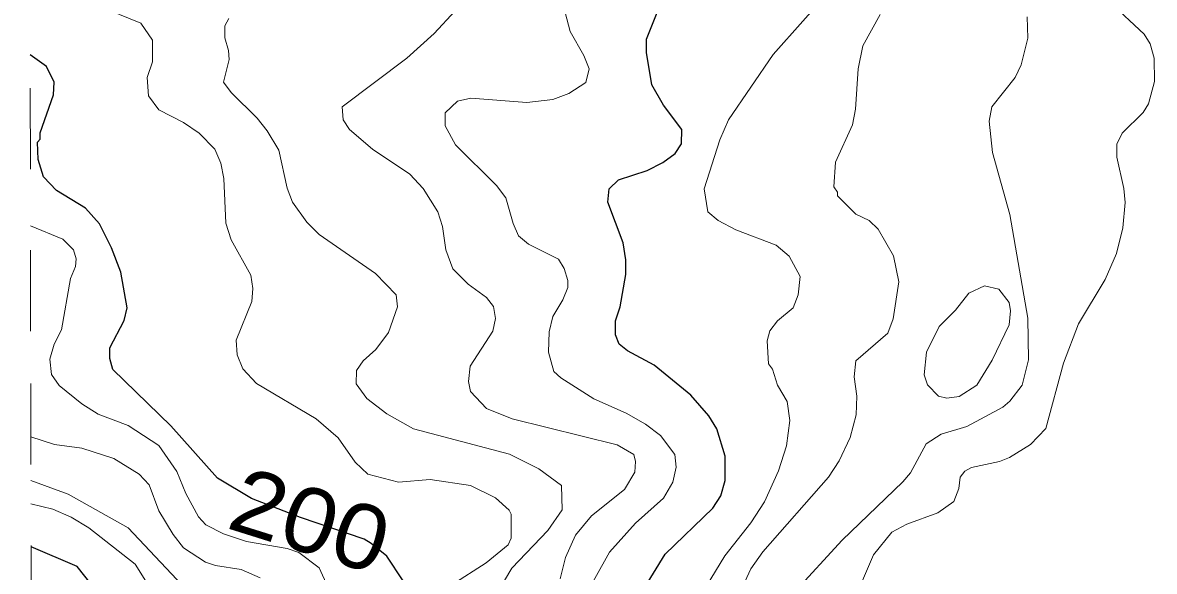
# Model space of a CAD drawing. Extents: x 474.5 to 500, y 7345.7 to 7373.4.
# Drawn here: x 474.522 to 475.921, y 7367.449 to 7368.127 of the extents above; entities that cross this region are included whole.
import ezdxf
from ezdxf.enums import TextEntityAlignment as Align

# ---------------------------------------------------------------- set-up
doc = ezdxf.new("R2010")
doc.units = 0
doc.header["$LTSCALE"] = 0.032
doc.linetypes.add('SHORT_DASHED', pattern=[2.7, 1.5, -1.2])
for name, color, linetype, lineweight in [('1', 7, 'Continuous', 25), ('2', 7, 'Continuous', 13), ('22', 7, 'SHORT_DASHED', 13)]:
    doc.layers.add(name, color=color, linetype=linetype, lineweight=lineweight)
doc.layers.add('61', color=7, linetype='Continuous')

msp = doc.modelspace()

# ---------------------------------------------------------------- linework, layer by layer
at = {"layer": '1'}
for points in [[(475.2879, 7367.4232), (475.3168, 7367.4701), (475.3756, 7367.5269), (475.3854, 7367.5423), (475.3909, 7367.5609), (475.391, 7367.5913), (475.3805, 7367.6247), (475.3706, 7367.6409), (475.3482, 7367.6664), (475.303, 7367.7036), (475.27, 7367.7211), (475.2598, 7367.7293), (475.2554, 7367.741), (475.2554, 7367.7584), (475.261, 7367.7755), (475.2681, 7367.8156), (475.2681, 7367.8337), (475.2646, 7367.8546), (475.2458, 7367.9048), (475.2475, 7367.9212), (475.259, 7367.9325), (475.2945, 7367.9441), (475.3139, 7367.9538), (475.3289, 7367.9652), (475.3367, 7367.9771), (475.3373, 7367.9949), (475.3145, 7368.0247), (475.3001, 7368.0497), (475.2937, 7368.09), (475.2937, 7368.1065), (475.3075, 7368.1415)], [(474.9929, 7367.4369), (474.9727, 7367.4674), (474.953, 7367.4832), (474.9446, 7367.4884), (474.8658, 7367.5155), (474.805, 7367.5389), (474.7631, 7367.5639), (474.7056, 7367.6285), (474.6336, 7367.698), (474.63, 7367.7118), (474.6301, 7367.7251), (474.6477, 7367.7588), (474.6514, 7367.7744), (474.6436, 7367.8184), (474.6321, 7367.8484), (474.6171, 7367.8781), (474.6001, 7367.8974), (474.5641, 7367.9195), (474.5478, 7367.9364), (474.5414, 7367.9576), (474.5406, 7367.9792), (474.5437, 7367.9829), (474.544, 7367.9905), (474.5605, 7368.0377), (474.5613, 7368.0533), (474.5519, 7368.0725), (474.5315, 7368.087)], [(474.5343, 7366.5127), (474.5346, 7366.5143), (474.5518, 7366.6004), (474.5614, 7366.6248), (474.5676, 7366.6297), (474.5718, 7366.6387), (474.5901, 7366.6634), (474.6044, 7366.7344), (474.6219, 7366.9636), (474.6148, 7367.1177), (474.634, 7367.2513), (474.6395, 7367.3409), (474.6346, 7367.3854), (474.6149, 7367.4232), (474.5898, 7367.4546), (474.5326, 7367.4792)]]:
    msp.add_lwpolyline(points, dxfattribs=at)
at = {"layer": '2'}
for points in [[(475.0828, 7368.1698), (475.0311, 7368.1135), (474.9974, 7368.0827), (474.9173, 7368.0225), (474.9185, 7368.0066), (474.9262, 7367.9949), (474.9549, 7367.9702), (475.0008, 7367.9394), (475.0175, 7367.9219), (475.0355, 7367.8931), (475.0415, 7367.8749), (475.0456, 7367.846), (475.0542, 7367.8225), (475.073, 7367.8035), (475.0956, 7367.7873), (475.1044, 7367.776), (475.1069, 7367.7614), (475.1037, 7367.7457), (475.0757, 7367.7021), (475.0735, 7367.6832), (475.0758, 7367.671), (475.0956, 7367.6498), (475.1274, 7367.6371), (475.2575, 7367.605), (475.2778, 7367.593), (475.2801, 7367.5845), (475.2793, 7367.5712), (475.2664, 7367.5501), (475.2256, 7367.5173), (475.2058, 7367.4934), (475.1935, 7367.4658), (475.1868, 7367.4396)], [(475.5236, 7368.1703), (475.4502, 7368.0873), (475.3951, 7368.0067), (475.3844, 7367.9819), (475.3647, 7367.9212), (475.3692, 7367.8929), (475.382, 7367.8823), (475.404, 7367.8707), (475.454, 7367.8517), (475.4699, 7367.8383), (475.4835, 7367.8132), (475.4811, 7367.7904), (475.4748, 7367.7745), (475.4555, 7367.7583), (475.4462, 7367.7458), (475.4429, 7367.7334), (475.4445, 7367.7052), (475.4493, 7367.6984), (475.4555, 7367.6787), (475.4675, 7367.6585), (475.4707, 7367.6351), (475.4668, 7367.6037), (475.4569, 7367.5729), (475.4393, 7367.5349), (475.4225, 7367.5087), (475.3903, 7367.4679), (475.3674, 7367.4301)], [(474.6289, 7368.1422), (474.6682, 7368.1261), (474.6826, 7368.1049), (474.6826, 7368.0781), (474.6763, 7368.059), (474.6778, 7368.0363), (474.6907, 7368.0191), (474.7211, 7368.0032), (474.7405, 7367.9902), (474.7597, 7367.9702), (474.7672, 7367.9529), (474.7711, 7367.9342), (474.7733, 7367.879), (474.7802, 7367.8584), (474.8045, 7367.8146), (474.807, 7367.7983), (474.8054, 7367.7823), (474.7863, 7367.7345), (474.7876, 7367.7163), (474.7946, 7367.699), (474.8113, 7367.6809), (474.885, 7367.6373), (474.9125, 7367.6138), (474.9332, 7367.5835), (474.9489, 7367.5687), (474.9868, 7367.5591), (475.0262, 7367.5622), (475.0759, 7367.5547), (475.1069, 7367.5398), (475.1236, 7367.5246), (475.1261, 7367.5196), (475.1261, 7367.4899), (475.1225, 7367.4814), (475.0953, 7367.4593), (475.0528, 7367.4321)], [(475.1954, 7367.3785), (475.248, 7367.4726), (475.2799, 7367.5085), (475.3146, 7367.5391), (475.3262, 7367.5588), (475.3302, 7367.5776), (475.3287, 7367.5931), (475.311, 7367.6166), (475.2923, 7367.6307), (475.2684, 7367.6442), (475.2285, 7367.6618), (475.1876, 7367.6878), (475.1788, 7367.6956), (475.1725, 7367.7196), (475.1733, 7367.7447), (475.1778, 7367.7636), (475.1902, 7367.7844), (475.1962, 7367.7994), (475.1963, 7367.8082), (475.1919, 7367.823), (475.1847, 7367.8345), (475.1478, 7367.8531), (475.1354, 7367.8632), (475.1285, 7367.8784), (475.1196, 7367.9103), (475.1081, 7367.9256), (475.0572, 7367.9759), (475.0448, 7367.9991), (475.0448, 7368.0153), (475.06, 7368.0296), (475.0764, 7368.0336), (475.1456, 7368.028), (475.1778, 7368.0318), (475.1977, 7368.0391), (475.2184, 7368.0529), (475.2225, 7368.0697), (475.2162, 7368.0861), (475.1992, 7368.1158), (475.1908, 7368.1472)], [(475.5424, 7367.3952), (475.5742, 7367.4691), (475.5971, 7367.4971), (475.6154, 7367.5069), (475.6537, 7367.5213), (475.6736, 7367.5353), (475.6797, 7367.551), (475.6814, 7367.5653), (475.687, 7367.5724), (475.6952, 7367.5773), (475.7302, 7367.5847), (475.7423, 7367.5894), (475.7683, 7367.6054), (475.7874, 7367.6255), (475.8091, 7367.7061), (475.8277, 7367.7545), (475.8607, 7367.8093), (475.8745, 7367.8417), (475.8824, 7367.8733), (475.8855, 7367.9047), (475.8839, 7367.9218), (475.8753, 7367.9605), (475.8752, 7367.9767), (475.8817, 7367.99), (475.9076, 7368.0156), (475.9143, 7368.0265), (475.9215, 7368.0542), (475.9213, 7368.0829), (475.9163, 7368.1006), (475.9088, 7368.1125), (475.8665, 7368.1519)], [(475.1181, 7367.4375), (475.1272, 7367.4529), (475.1717, 7367.4991), (475.1891, 7367.525), (475.1883, 7367.5549), (475.1606, 7367.5756), (475.124, 7367.5935), (475.0054, 7367.625), (474.9725, 7367.6436), (474.9479, 7367.6623), (474.9347, 7367.6803), (474.9349, 7367.697), (474.9433, 7367.7089), (474.959, 7367.7229), (474.9744, 7367.7439), (474.9856, 7367.7755), (474.9841, 7367.7903), (474.9584, 7367.8169), (474.8889, 7367.8648), (474.8736, 7367.8802), (474.8558, 7367.905), (474.8491, 7367.9221), (474.8389, 7367.969), (474.8245, 7367.993), (474.8122, 7368.0085), (474.7801, 7368.0406), (474.7704, 7368.0532), (474.7776, 7368.0813), (474.7769, 7368.0921), (474.772, 7368.1078), (474.772, 7368.1227), (474.777, 7368.1319)], [(475.4076, 7367.42), (475.4227, 7367.4519), (475.4374, 7367.473), (475.5184, 7367.5652), (475.5318, 7367.5854), (475.5453, 7367.6142), (475.5529, 7367.642), (475.5537, 7367.6654), (475.5505, 7367.6892), (475.5522, 7367.709), (475.5918, 7367.7432), (475.5986, 7367.7606), (475.6056, 7367.8064), (475.5991, 7367.8385), (475.5802, 7367.8715), (475.5688, 7367.8821), (475.5524, 7367.8899), (475.5298, 7367.9127), (475.5297, 7367.9172), (475.5251, 7367.9238), (475.5274, 7367.9544), (475.5483, 7368.0003), (475.5521, 7368.0199), (475.5553, 7368.0695), (475.5609, 7368.0981), (475.5826, 7368.1368)], [(475.7643, 7368.1337), (475.7651, 7368.1076), (475.7567, 7368.0747), (475.7494, 7368.0588), (475.7205, 7368.0225), (475.7173, 7368.005), (475.7212, 7367.9661), (475.7427, 7367.8895), (475.7651, 7367.7616), (475.7659, 7367.7101), (475.7579, 7367.6787), (475.7429, 7367.6589), (475.7342, 7367.6517), (475.6895, 7367.6278), (475.6577, 7367.6181), (475.6392, 7367.6062), (475.6198, 7367.5707), (475.6107, 7367.5594), (475.5353, 7367.4872), (475.4758, 7367.4221)], [(474.5319, 7367.8758), (474.5719, 7367.8594), (474.5852, 7367.8462), (474.5884, 7367.835), (474.5876, 7367.8255), (474.5812, 7367.8108), (474.5701, 7367.7473), (474.5612, 7367.7295), (474.5558, 7367.7109), (474.558, 7367.6919), (474.5672, 7367.6783), (474.5952, 7367.6558), (474.6156, 7367.6429), (474.6525, 7367.6291), (474.6906, 7367.6043), (474.7127, 7367.572), (474.7239, 7367.5449), (474.7395, 7367.516), (474.7488, 7367.5064), (474.7706, 7367.495), (474.799, 7367.4856), (474.8494, 7367.477), (474.8638, 7367.472), (474.889, 7367.4531), (474.8996, 7367.4295)], [(474.8158, 7367.4409), (474.7926, 7367.4513), (474.7605, 7367.4562), (474.7483, 7367.4602), (474.7212, 7367.478), (474.7083, 7367.4942), (474.6907, 7367.5237), (474.6785, 7367.5558), (474.6662, 7367.569), (474.635, 7367.5884), (474.5954, 7367.6012), (474.5616, 7367.6055), (474.5323, 7367.6151)], [(474.7332, 7367.4175), (474.6527, 7367.5027), (474.5783, 7367.5441), (474.5324, 7367.5609)], [(474.5325, 7367.5322), (474.5595, 7367.5256), (474.5823, 7367.5158), (474.6042, 7367.5025), (474.6614, 7367.4578), (474.6808, 7367.4269), (474.6937, 7367.393), (474.7001, 7367.349), (474.6993, 7367.283), (474.6546, 7367.1439), (474.645, 7367.0992), (474.6445, 7367.0499), (474.6555, 7366.9988), (474.6578, 7366.941), (474.6386, 7366.8337), (474.6332, 7366.7762), (474.6315, 7366.7132), (474.6172, 7366.6195), (474.5933, 7366.5413), (474.5551, 7366.4632), (474.5351, 7366.4318), (474.5344, 7366.4307)]]:
    msp.add_lwpolyline(points, dxfattribs=at)
msp.add_lwpolyline([(475.6553, 7367.7515), (475.6755, 7367.7714), (475.6919, 7367.7926), (475.7114, 7367.8014), (475.7291, 7367.7975), (475.7418, 7367.7811), (475.7436, 7367.7708), (475.7419, 7367.7533), (475.7209, 7367.7099), (475.7022, 7367.6788), (475.68, 7367.6647), (475.6649, 7367.6628), (475.6545, 7367.6651), (475.6409, 7367.6792), (475.6367, 7367.6914), (475.6396, 7367.7194)], close=True, dxfattribs=at)
at = {"layer": '22'}
msp.add_lwpolyline([(474.5381, 7364.3565), (474.5371, 7364.9213), (474.5361, 7365.4862), (474.5351, 7366.0511), (474.5341, 7366.616), (474.5331, 7367.1808), (474.5321, 7367.7457), (474.5311, 7368.3105), (474.5301, 7368.8754), (474.5291, 7369.4403), (474.5281, 7370.0051), (474.5272, 7370.57), (474.5262, 7371.1349), (474.5252, 7371.6997), (474.5242, 7372.2646), (474.5232, 7372.8295), (474.5222, 7373.3943)], dxfattribs=at)

# ---------------------------------------------------------------- texts
at = {"layer": '61', "width": 1.1}
msp.add_text('200', height=0.08, rotation=342.582, dxfattribs=at).set_placement((474.8658, 7367.4736), align=Align.CENTER)

doc.saveas('drawing.dxf')
